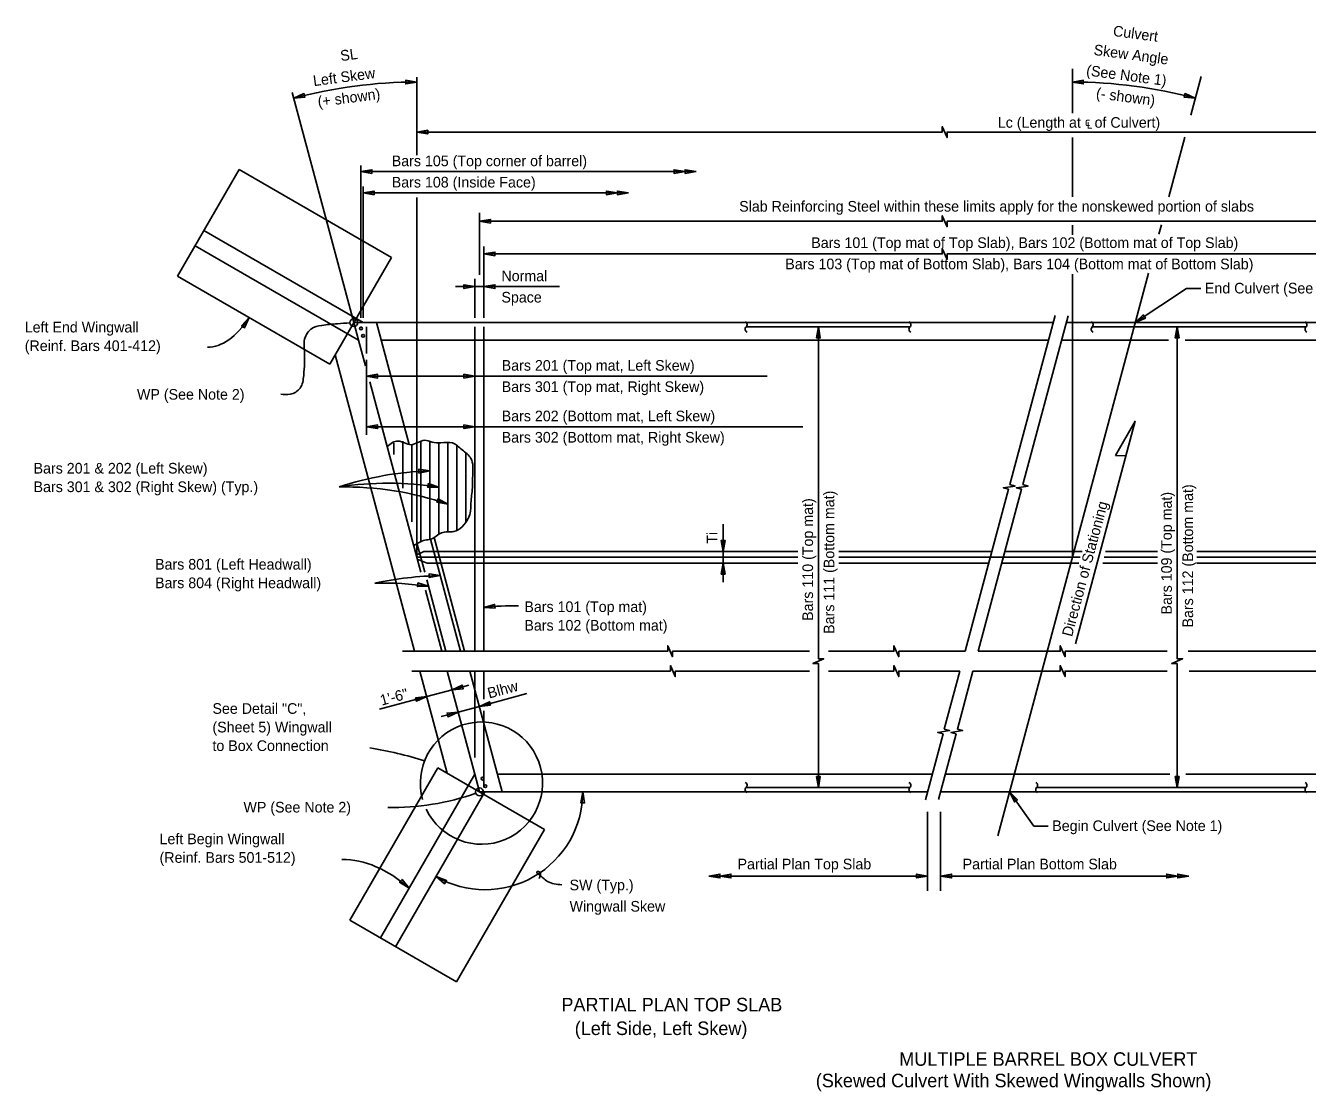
# Model space of a CAD drawing. Extents: x 6 to 221, y -2 to 90.
# Drawn here: x 6.5 to 79.3, y 23 to 83.5 of the extents above; entities that cross this region are included whole.
import ezdxf

# ---------------------------------------------------------------- set-up
doc = ezdxf.new("R2010")
doc.units = 0
for name, color, linetype in [('AdhocPoint_dp', 7, 'Continuous'), ('CL_Major', 7, 'Continuous'), ('Leader', 7, 'Continuous'), ('PlotBorder_dp', 7, 'Continuous'), ('Rebar', 7, 'Continuous'), ('Symbols', 7, 'Continuous'), ('WallConc', 7, 'Continuous'), ('WallConc_h', 7, 'Continuous')]:
    doc.layers.add(name, color=color, linetype=linetype)

msp = doc.modelspace()

# ---------------------------------------------------------------- linework, layer by layer
at = {"layer": 'AdhocPoint_dp'}
msp.add_lwpolyline([(68.438, 59.09), (69.03, 59.079), (69.555, 61.037)], close=True, dxfattribs=at)
at = {"layer": 'CL_Major'}
for p, q in [((73.305, 80.62), (72.717, 78.425)), ((72.384, 77.184), (71.475, 73.793)), ((71.051, 72.208), (70.907, 71.671)), ((70.311, 69.447), (61.748, 37.49)), ((28.718, 53.313), (50.393, 53.313)), ((52.71, 53.313), (66.441, 53.313)), ((67.797, 53.313), (70.83, 53.313)), ((73.061, 53.313), (103.258, 53.313))]:
    msp.add_line(p, q, dxfattribs=at)
at = {"layer": 'Leader'}
for p, q in [((72.478, 68.586), (69.56, 66.646)), ((73.294, 68.586), (72.478, 68.586)), ((63.803, 38.04), (62.415, 39.979)), ((64.619, 38.04), (63.803, 38.04))]:
    msp.add_line(p, q, dxfattribs=at)
for centre, radius, start, end in [((30.056, 39.964), 18.27, 91.85951, 108.34211), ((27.113, 39.252), 18.27, 80.98357, 98.83534), ((24.605, 39.038), 18.27, 71.21273, 90.93565), ((30.588, 31.488), 20.795, 91.4695, 101.76673), ((26.652, 31.053), 20.795, 82.42161, 90.83913), ((34.259, 36.372), 14.186, 89.01032, 96.95694), ((21.772, 17.442), 25.407, 73.07904, 80.27913), ((27.324, 53.41), 14.32, 268.98569, 289.40418)]:
    msp.add_arc(centre, radius, start, end, dxfattribs=at)
for centre, major_axis, ratio, start_param, end_param in [((16.701, 84.542), (-0.121, 19.302), 0.303561, 3.141593, 3.560708), ((25.628, 21.124), (1.568, -14.986), 0.534795, 2.616554, 3.090575)]:
    msp.add_ellipse(centre, major_axis=major_axis, ratio=ratio, start_param=start_param, end_param=end_param, dxfattribs=at)
for points in [[(20.99, 62.579), (21.527, 62.575), (22.09, 62.922), (22.295, 63.647), (22.335, 65.031), (22.326, 65.6), (22.709, 66.275), (23.322, 66.489), (24.211, 66.578), (24.923, 66.63)], [(36.96, 34.703), (36.161, 34.89), (35.618, 35.31), (35.546, 35.378), (35.546, 35.437), (35.623, 35.455), (35.679, 35.446), (35.754, 35.374), (35.754, 35.299), (35.723, 35.146), (35.667, 35.067)]]:
    msp.add_spline(points, degree=3, dxfattribs=at)
at = {"layer": 'PlotBorder_dp'}
for p, q in [((65.988, 81.066), (65.988, 78.536)), ((28.718, 80.589), (28.718, 76.154)), ((21.643, 79.715), (25.145, 66.646)), ((65.988, 77.171), (65.988, 73.79)), ((25.552, 75.568), (25.552, 66.913)), ((25.552, 75.223), (44.603, 75.223)), ((25.668, 74.38), (25.668, 66.913)), ((25.668, 74.014), (40.751, 74.014)), ((28.718, 73.761), (28.718, 53.313)), ((32.284, 72.884), (32.284, 69.361)), ((65.988, 72.186), (65.988, 71.624)), ((32.54, 70.96), (32.54, 66.913)), ((65.988, 69.403), (65.988, 53.313)), ((30.92, 68.687), (32.028, 68.687)), ((32.028, 69.124), (32.028, 66.913)), ((32.028, 68.687), (32.54, 68.687)), ((32.54, 68.687), (36.845, 68.687)), ((25.413, 65.646), (25.145, 66.646)), ((25.145, 66.646), (25.681, 66.646)), ((25.873, 64.53), (25.873, 60.262)), ((25.873, 63.603), (32.028, 63.603)), ((32.028, 63.603), (48.635, 63.603)), ((25.873, 60.729), (32.028, 60.729)), ((32.028, 60.729), (50.67, 60.729)), ((69.555, 61.037), (66.164, 48.383)), ((46.139, 55.185), (46.139, 53.646)), ((46.139, 53.646), (46.139, 52.979)), ((46.139, 52.979), (46.139, 51.895)), ((30.736, 45.781), (31.685, 46.035)), ((26.597, 44.672), (29.287, 45.393)), ((29.287, 45.393), (30.736, 45.781)), ((32.282, 44.841), (34.98, 45.564)), ((30.118, 44.261), (31.075, 44.517)), ((31.075, 44.517), (32.282, 44.841)), ((32.29, 39.979), (32.022, 40.979)), ((32.29, 39.979), (32.6, 39.979)), ((57.756, 38.838), (57.756, 34.362)), ((58.497, 38.838), (58.497, 34.362)), ((57.756, 35.2), (45.332, 35.2)), ((72.603, 35.2), (58.497, 35.2))]:
    msp.add_line(p, q, dxfattribs=at)
for points in [[(28.718, 80.313), (28.093, 80.419), (28.093, 80.207)], [(65.988, 80.313), (66.612, 80.207), (66.612, 80.419)], [(21.73, 79.393), (22.361, 79.452), (22.306, 79.657)], [(72.976, 79.393), (72.4, 79.657), (72.345, 79.452)], [(28.718, 77.469), (29.343, 77.363), (29.343, 77.575)], [(25.552, 75.223), (26.177, 75.118), (26.177, 75.329)], [(43.979, 75.223), (43.354, 75.329), (43.354, 75.118)], [(44.603, 75.223), (43.979, 75.329), (43.979, 75.118)], [(25.668, 74.014), (26.293, 73.908), (26.293, 74.12)], [(40.126, 74.014), (39.502, 74.12), (39.502, 73.908)], [(40.751, 74.014), (40.126, 74.12), (40.126, 73.908)], [(32.284, 72.406), (32.909, 72.3), (32.909, 72.512)], [(32.54, 70.546), (33.165, 70.44), (33.165, 70.652)], [(32.028, 68.687), (31.403, 68.793), (31.403, 68.582)], [(32.54, 68.687), (33.165, 68.582), (33.165, 68.793)], [(69.56, 66.646), (70.139, 66.904), (70.022, 67.08)], [(19.196, 66.926), (18.76, 66.467), (18.935, 66.349)], [(51.551, 66.396), (51.446, 65.771), (51.657, 65.771)], [(71.946, 66.396), (71.84, 65.771), (72.052, 65.771)], [(25.873, 63.603), (26.498, 63.709), (26.498, 63.497)], [(32.028, 63.603), (31.403, 63.497), (31.403, 63.709)], [(25.873, 60.729), (26.498, 60.835), (26.498, 60.623)], [(32.028, 60.729), (31.403, 60.623), (31.403, 60.835)], [(29.463, 58.224), (28.835, 58.309), (28.842, 58.098)], [(29.976, 57.296), (29.376, 57.499), (29.343, 57.29)], [(30.489, 56.334), (29.932, 56.636), (29.863, 56.435)], [(46.139, 53.646), (46.245, 54.271), (46.034, 54.271)], [(46.139, 52.979), (46.034, 52.355), (46.245, 52.355)], [(29.394, 51.666), (28.789, 51.854), (28.761, 51.644)], [(30.055, 52.276), (29.427, 52.366), (29.433, 52.154)], [(32.54, 50.453), (33.173, 50.424), (33.148, 50.634)], [(30.736, 45.781), (31.367, 45.84), (31.312, 46.045)], [(29.287, 45.393), (28.656, 45.333), (28.711, 45.129)], [(31.075, 44.517), (30.444, 44.458), (30.498, 44.253)], [(32.282, 44.841), (32.913, 44.9), (32.858, 45.105)], [(51.551, 40.229), (51.657, 40.854), (51.446, 40.854)], [(71.946, 40.229), (72.052, 40.854), (71.84, 40.854)], [(38.16, 39.979), (38.054, 39.355), (38.265, 39.355)], [(62.415, 39.979), (62.693, 39.41), (62.865, 39.533)], [(28.289, 34.512), (27.889, 35.004), (27.749, 34.845)], [(29.82, 35.165), (30.308, 34.761), (30.414, 34.944)], [(45.332, 35.2), (45.957, 35.094), (45.957, 35.306)], [(45.957, 35.2), (46.582, 35.094), (46.582, 35.306)], [(57.756, 35.2), (57.131, 35.306), (57.131, 35.094)], [(58.497, 35.2), (59.121, 35.094), (59.121, 35.306)], [(71.979, 35.2), (71.354, 35.306), (71.354, 35.094)], [(72.603, 35.2), (71.979, 35.306), (71.979, 35.094)]]:
    msp.add_lwpolyline(points, close=True, dxfattribs=at)
for centre in [(25.145, 66.646), (32.29, 39.979)]:
    msp.add_circle(centre, 0.222, dxfattribs=at)
for centre, radius, start, end in [((28.718, 53.313), 27, 90, 105), ((65.988, 53.313), 27, 75, 90), ((47.57, 66.268), 0.179, 134.1793, 245.90652), ((47.321, 66.524), 0.179, 314.1793, 65.90652), ((56.88, 66.268), 0.179, 134.1793, 245.90652), ((56.63, 66.524), 0.179, 314.1793, 65.90652), ((67.24, 66.268), 0.179, 134.1793, 245.90652), ((66.991, 66.524), 0.179, 314.1793, 65.90652), ((79.394, 66.268), 0.179, 134.1793, 245.90652), ((79.145, 66.524), 0.179, 314.1793, 65.90652), ((32.401, 40.479), 3.475, 205.38636, 195.64146), ((47.57, 40.101), 0.179, 134.1793, 245.90652), ((47.321, 40.358), 0.179, 314.1793, 65.90652), ((56.88, 40.101), 0.179, 134.1793, 245.90652), ((56.63, 40.358), 0.179, 314.1793, 65.90652), ((64.085, 40.101), 0.179, 134.1793, 245.90652), ((63.836, 40.358), 0.179, 314.1793, 65.90652), ((79.394, 40.101), 0.179, 134.1793, 245.90652), ((79.145, 40.358), 0.179, 314.1793, 65.90652), ((32.6, 39.979), 5.56, 240, 0)]:
    msp.add_arc(centre, radius, start, end, dxfattribs=at)
at = {"layer": 'Rebar'}
for p, q in [((25.873, 64.895), (25.873, 66.396)), ((32.028, 47.971), (32.028, 66.396)), ((32.54, 47.971), (32.54, 66.396)), ((47.446, 66.396), (56.755, 66.396)), ((67.116, 66.396), (79.27, 66.396)), ((27.412, 59.153), (27.412, 59.793)), ((27.925, 57.239), (27.925, 59.901)), ((28.95, 54.164), (28.95, 59.93)), ((29.463, 54.326), (29.463, 59.885)), ((29.976, 54.618), (29.976, 59.831)), ((30.489, 54.731), (30.489, 59.828)), ((28.438, 55.325), (28.438, 59.711)), ((31.002, 54.868), (31.002, 59.669)), ((31.515, 55.317), (31.515, 59.253)), ((28.752, 54.065), (29.179, 52.469)), ((29.503, 54.334), (31.208, 47.971)), ((29.298, 52.025), (30.384, 47.971)), ((32.028, 41.926), (32.028, 46.844)), ((32.54, 45.251), (32.54, 46.844)), ((32.54, 40.229), (32.54, 44.579)), ((47.446, 40.229), (56.755, 40.229)), ((63.96, 40.229), (79.27, 40.229))]:
    msp.add_line(p, q, dxfattribs=at)
for centre in [(25.552, 66.316), (25.668, 65.893), (32.46, 40.733), (32.62, 40.309)]:
    msp.add_circle(centre, 0.08, dxfattribs=at)
at = {"layer": 'Symbols'}
for points in [[(28.718, 77.469), (58.596, 77.469), (58.596, 77.779), (58.866, 77.159), (58.866, 77.469), (103.258, 77.469)], [(32.284, 72.406), (58.596, 72.406), (58.596, 72.716), (58.866, 72.096), (58.866, 72.406), (101.244, 72.406)], [(32.54, 70.546), (58.596, 70.546), (58.596, 70.856), (58.866, 70.236), (58.866, 70.546), (100.988, 70.546)], [(59.897, 47.971), (62.364, 57.178), (62.065, 57.258), (62.734, 57.359), (62.434, 57.439), (65.008, 67.044)], [(60.638, 47.971), (63.105, 57.178), (62.806, 57.258), (63.474, 57.359), (63.175, 57.439), (65.746, 67.036)], [(51.551, 40.229), (51.551, 47.272), (51.241, 47.272), (51.861, 47.542), (51.551, 47.542), (51.551, 66.396)], [(71.946, 40.229), (71.946, 47.272), (71.636, 47.272), (72.256, 47.542), (71.946, 47.542), (71.946, 66.396)], [(27.92, 47.971), (42.992, 47.971), (42.992, 48.281), (43.262, 47.661), (43.262, 47.971), (51.047, 47.971)], [(52.126, 47.971), (55.849, 47.971), (55.849, 48.281), (56.119, 47.661), (56.119, 47.971), (59.897, 47.971)], [(60.638, 47.971), (65.303, 47.971), (65.303, 48.281), (65.573, 47.661), (65.573, 47.971), (71.382, 47.971)], [(72.58, 47.971), (81.457, 47.971), (81.457, 48.281), (81.727, 47.661), (81.727, 47.971), (103.984, 47.971)], [(28.433, 46.844), (43.143, 46.844), (43.143, 47.154), (43.413, 46.534), (43.413, 46.844), (51.047, 46.844)], [(52.126, 46.844), (55.849, 46.844), (55.849, 47.154), (56.119, 46.534), (56.119, 46.844), (59.595, 46.844)], [(57.634, 39.526), (58.641, 43.281), (58.341, 43.361), (59.01, 43.462), (58.711, 43.542), (59.595, 46.844)], [(58.382, 39.551), (59.381, 43.281), (59.082, 43.361), (59.751, 43.462), (59.451, 43.542), (60.336, 46.844)], [(60.336, 46.844), (65.303, 46.844), (65.303, 47.154), (65.573, 46.534), (65.573, 46.844), (71.382, 46.844)], [(72.628, 46.844), (81.306, 46.844), (81.306, 47.154), (81.576, 46.534), (81.576, 46.844), (103.838, 46.844)]]:
    msp.add_lwpolyline(points, dxfattribs=at)
at = {"layer": 'WallConc'}
for p, q in [((18.619, 75.342), (15.119, 69.28)), ((18.619, 75.342), (27.279, 70.342)), ((16.619, 71.878), (25.681, 66.646)), ((16.119, 71.012), (25.413, 65.646)), ((23.779, 64.28), (27.279, 70.342)), ((15.119, 69.28), (23.779, 64.28)), ((25.681, 66.646), (64.901, 66.646)), ((26.439, 66.646), (28.295, 59.721)), ((65.642, 66.646), (106.294, 66.646)), ((25.413, 65.646), (25.803, 64.19)), ((65.374, 65.646), (71.456, 65.646)), ((72.402, 65.646), (106.562, 65.646)), ((24.084, 64.809), (28.596, 47.971)), ((26.049, 63.274), (28.945, 52.466)), ((29.712, 54.433), (31.443, 47.971)), ((62.159, 53.646), (66.543, 53.646)), ((67.871, 53.646), (70.83, 53.646)), ((73.061, 53.646), (102.847, 53.646)), ((61.98, 52.979), (66.36, 52.979)), ((67.715, 52.979), (70.83, 52.979)), ((73.061, 52.979), (102.668, 52.979)), ((29.218, 51.445), (30.149, 47.971)), ((28.898, 46.844), (30.453, 41.04)), ((30.451, 46.844), (32.022, 40.979)), ((31.745, 46.844), (33.585, 39.979)), ((24.924, 32.685), (29.924, 41.346)), ((26.656, 31.685), (32.022, 40.979)), ((29.924, 41.346), (35.987, 37.846)), ((58.765, 40.979), (71.526, 40.979)), ((72.445, 40.979), (99.953, 40.979)), ((27.522, 31.185), (32.6, 39.979)), ((32.6, 39.979), (57.756, 39.979)), ((58.497, 39.979), (99.376, 39.979)), ((30.987, 29.185), (35.987, 37.846)), ((30.987, 29.185), (24.924, 32.685))]:
    msp.add_line(p, q, dxfattribs=at)
msp.add_spline([(28.544, 53.961), (29.186, 54.282), (29.528, 54.34), (30.133, 54.702), (30.827, 54.776), (31.643, 55.506), (31.753, 55.809), (31.802, 56.389), (31.884, 57.265), (31.9, 57.978), (31.802, 58.929), (31.302, 59.415), (30.751, 59.809), (30.088, 59.812), (29.596, 59.859), (29.159, 59.959), (28.405, 59.707), (27.664, 59.917), (27.031, 59.607)], degree=3, dxfattribs=at)
at = {"layer": 'WallConc_h'}
for p, q in [((26.707, 65.646), (64.633, 65.646)), ((28.693, 53.425), (29.128, 53.646)), ((28.748, 53.202), (29.307, 52.979)), ((29.128, 53.646), (50.393, 53.646)), ((52.71, 53.646), (61.418, 53.646)), ((29.307, 52.979), (50.393, 52.979)), ((52.71, 52.979), (61.239, 52.979)), ((33.317, 40.979), (58.024, 40.979))]:
    msp.add_line(p, q, dxfattribs=at)

# ---------------------------------------------------------------- texts
at = {"layer": 'AdhocPoint_dp'}
for s, rotation, p in [('Culvert', 352.5, (68.276, 82.934)), ('Skew Angle', 352.5, (67.174, 81.859)), ('(See Note 1)', 352.5, (66.753, 80.694)), ('(- shown)', 352.5, (67.309, 79.401)), ('Bars 111 (Bottom mat)', 90, (52.459, 48.96)), ('Bars 109 (Top mat)', 90, (71.643, 50.058)), ('Bars 112 (Bottom mat)', 90, (72.853, 49.32)), ('Bars 110 (Top mat)', 90, (51.249, 49.698)), ('Direction of Stationing', 75, (65.969, 48.761)), ('Ti', 90, (45.815, 54.08)), ('Blhw', 15, (32.838, 45.282)), ('1\'-6"', 15, (26.725, 44.877))]:
    msp.add_text(s, height=0.6048, rotation=rotation, dxfattribs=at).set_placement(p)
for s, height, p in [('Lc (Length at ℄ of Culvert)', 0.6048, (61.753, 77.717)), ('Bars 105 (Top corner of barrel)', 0.6048, (27.3, 75.532)), ('Bars 108 (Inside Face)', 0.6048, (27.3, 74.322)), ('Slab Reinforcing Steel within these limits apply for the nonskewed portion of slabs', 0.6048, (47.051, 72.951)), ('Bars 101 (Top mat of Top Slab), Bars 102 (Bottom mat of Top Slab)', 0.6048, (51.147, 70.884)), ('Bars 103 (Top mat of Bottom Slab), Bars 104 (Bottom mat of Bottom Slab)', 0.6048, (49.672, 69.674)), ('Normal', 0.6048, (33.535, 68.996)), ('End Culvert (See Note 1)', 0.6048, (73.523, 68.301)), ('Space', 0.6048, (33.535, 67.786)), ('Left End Wingwall', 0.6048, (6.438, 66.085)), ('(Reinf. Bars 401-412)', 0.6048, (6.438, 65.029)), ('Bars 201 (Top mat, Left Skew)', 0.6048, (33.551, 63.911)), ('WP (See Note 2)', 0.6048, (12.818, 62.266)), ('Bars 301 (Top mat, Right Skew)', 0.6048, (33.551, 62.702)), ('Bars 202 (Bottom mat, Left Skew)', 0.6048, (33.551, 61.037)), ('Bars 302 (Bottom mat, Right Skew)', 0.6048, (33.551, 59.827)), ('Bars 201 & 202 (Left Skew)', 0.6048, (6.939, 58.069)), ('Bars 301 & 302 (Right Skew) (Typ.)', 0.6048, (6.939, 57.013)), ('Bars 801 (Left Headwall)', 0.6048, (13.846, 52.611)), ('Bars 804 (Right Headwall)', 0.6048, (13.846, 51.555)), ('Bars 101 (Top mat)', 0.6048, (34.84, 50.199)), ('Bars 102 (Bottom mat)', 0.6048, (34.84, 49.143)), ('See Detail "C",', 0.6048, (17.108, 44.415)), ('(Sheet 5) Wingwall', 0.6048, (17.108, 43.359)), ('to Box Connection', 0.6048, (17.108, 42.303)), ('WP (See Note 2)', 0.6048, (18.871, 38.809)), ('Begin Culvert (See Note 1)', 0.6048, (64.847, 37.755)), ('Left Begin Wingwall', 0.6048, (14.101, 37.007)), ('(Reinf. Bars 501-512)', 0.6048, (14.101, 35.951)), ('Partial Plan Top Slab', 0.6048, (46.958, 35.578)), ('Partial Plan Bottom Slab', 0.6048, (59.753, 35.578)), ('SW (Typ.)', 0.6048, (37.409, 34.388)), ('Wingwall Skew', 0.6048, (37.409, 33.178)), ('PARTIAL PLAN TOP SLAB', 0.768, (36.943, 27.508)), ('(Left Side, Left Skew)', 0.768, (37.701, 26.164)), ('MULTIPLE BARREL BOX CULVERT', 0.768, (56.149, 24.415)), ('(Skewed Culvert With Skewed Wingwalls Shown)', 0.768, (51.405, 23.196))]:
    msp.add_text(s, height=height, dxfattribs=at).set_placement(p)
at = {"layer": 'Leader'}
for s, p in [('SL', (24.416, 81.502)), ('Left Skew', (22.869, 80.078)), ('(+ shown)', (23.131, 78.893))]:
    msp.add_text(s, height=0.6048, rotation=7.5, dxfattribs=at).set_placement(p)

doc.saveas('drawing.dxf')
